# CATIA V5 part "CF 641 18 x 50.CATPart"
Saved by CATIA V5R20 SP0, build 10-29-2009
Part number: CF 641 18 x 50
Definition: NONE
Nomenclature: CF 641 18 x 50
Source: Unknown
Description: CF 641 18 x 50
Bounding box of the stored display mesh (mm): x -32 to 18, y -17 to 17, z -17 to 17
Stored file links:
  C:\Users\Utente\Desktop\IO LAVORO\3D X SITO CF\X SITO\CF 641\CF 641 18 x 50.CATPart
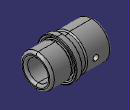
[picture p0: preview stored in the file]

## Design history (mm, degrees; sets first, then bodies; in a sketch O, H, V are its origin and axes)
Body1 "CF 641 18 x 50" (main body)
  Solid1: solid without history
